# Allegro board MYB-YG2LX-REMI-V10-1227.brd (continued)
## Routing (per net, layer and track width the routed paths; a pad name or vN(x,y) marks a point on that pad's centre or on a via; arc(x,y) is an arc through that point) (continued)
TX1_DN: length 44.4
  TOP w0.13: U11.27 20.34,28.71 20.34,29.22 20.06,29.5 20.06,29.88 v1(20.23,30.04) ; U12.C4 22.64,13.77 22.64,13.92 22.3,14.27 22.3,14.89 v1(22.12,15.06)
  ART03 w0.109: v1(22.12,15.06) 22.29,15.22 22.29,15.95 20.03,18.21 17.7,18.21 17,18.91 17,19.34 17.32,19.65 17.32,19.81 17.01,20.12 16.85,20.12 16.6,19.86 16.14,19.86 14.45,21.56 14.45,26.49 14.83,26.87 15.87,26.87 16.18,26.57 17.06,26.57 17.47,26.98 17.47,27.6 17.36,27.71 16.71,27.71 16.4,28.01 16.4,28.37 16.3,28.48 15.11,28.48 14.81,28.78 14.81,31.06 14.05,31.82 14.05,32.24 14.55,32.74 14.98,32.74 15.77,31.95 16.12,31.95 16.53,32.37 16.53,34.22 16.84,34.52 17.58,34.52 17.88,34.22 17.88,32.72 17.99,32.61 19.76,32.61 20.06,32.31 20.06,30.21 v1(20.23,30.04)
TX1_DN_OUT: length 2.8
  TOP w0.13: U12.A4 22.61,12.45 22.46,12.31 22.46,11.98 22.13,11.64 J7.6
TX1_DP: length 44.4
  TOP w0.13: U11.28 20.01,28.7 20.01,29.08 19.73,29.36 19.73,29.88 v1(19.57,30.04) ; U12.C3 22.97,13.77 22.97,14.06 22.62,14.41 22.62,14.9 v1(22.78,15.06)
  ART03 w0.109: v1(19.57,30.04) 19.73,30.21 19.73,32.18 19.62,32.29 17.85,32.29 17.55,32.59 17.55,34.08 17.44,34.19 16.97,34.19 16.86,34.08 16.86,32.23 16.25,31.62 15.64,31.62 14.84,32.42 14.69,32.42 14.38,32.11 14.38,31.95 15.13,31.2 15.13,28.91 15.24,28.8 16.43,28.8 16.73,28.5 16.73,28.15 16.84,28.04 17.5,28.04 17.8,27.74 17.8,26.85 17.19,26.24 16.04,26.24 15.74,26.55 14.97,26.55 14.78,26.36 14.78,21.69 16.28,20.19 16.46,20.19 16.72,20.44 17.14,20.44 17.65,19.94 17.65,19.52 17.33,19.2 17.33,19.05 17.84,18.54 20.17,18.54 22.62,16.09 22.62,15.89 22.71,15.79 23.17,15.79 23.26,15.7 23.26,15.56 23.17,15.47 22.71,15.47 22.62,15.37 22.62,15.22 v1(22.78,15.06)
TX1_DP_OUT: length 2.8
  TOP w0.13: J7.4 23.13,11.52 22.79,11.85 22.79,12.17 22.94,12.32 22.94,12.86 U12.A3
TX2_DN: length 44.6
  TOP w0.13: v1(19.31,30.56) 19.15,30.39 19.15,29.36 19.18,29.33 U11.30 ; v1(23.63,15.06) 23.79,14.9 23.79,14.37 23.44,14.02 23.44,13.77 U12.C2
  ART03 w0.109: v1(19.31,30.56) 19.15,30.73 19.15,30.99 18.85,31.29 16.93,31.29 16.51,30.87 16.51,29.56 16.83,29.24 18.18,29.24 18.51,28.91 19.55,28.91 19.66,28.8 19.66,28.02 19.55,27.91 18.71,27.91 18.41,27.61 18.41,25.63 18.2,25.42 16.15,25.42 15.74,25.02 15.74,22.3 16.07,21.97 17.2,21.97 17.52,22.3 17.52,23.87 17.63,23.98 18,23.98 18.11,23.87 18.11,20.93 18.41,20.62 19.2,20.62 19.5,20.93 19.5,22.02 19.61,22.13 21.94,22.13 22.05,22.02 22.05,21.37 21.93,21.26 20.46,21.26 20.16,20.96 20.16,19.38 22.17,17.37 22.7,17.37 23.8,16.27 23.8,15.22 v1(23.63,15.06)
TX2_DN_OUT: length 3
  TOP w0.13: J7.3 23.63,11.56 23.96,11.9 23.96,11.97 23.47,12.47 23.47,12.88 U12.A2
TX2_DP: length 44.6
  TOP w0.13: U11.31 18.78,29.33 18.82,29.36 18.82,30.39 v1(18.65,30.56) ; v1(24.29,15.06) 24.12,14.89 24.12,14.24 23.77,13.89 23.77,13.77 U12.C1
  ART03 w0.109: v1(18.65,30.56) 18.82,30.73 18.82,30.86 18.71,30.97 17.07,30.97 16.84,30.73 16.84,29.7 16.97,29.57 18.31,29.57 18.64,29.24 19.69,29.24 19.99,28.93 19.99,27.89 19.69,27.58 18.85,27.58 18.74,27.48 18.74,25.5 18.33,25.1 16.28,25.1 16.07,24.88 16.07,22.44 16.21,22.3 17.06,22.3 17.19,22.43 17.19,24.01 17.5,24.31 18.14,24.31 18.44,24.01 18.44,21.06 18.55,20.95 19.07,20.95 19.18,21.06 19.18,22.15 19.48,22.45 22.07,22.45 22.37,22.15 22.37,21.23 22.07,20.93 20.6,20.93 20.49,20.82 20.49,19.51 22.31,17.7 22.83,17.7 24.13,16.41 24.13,16.09 24.22,15.99 24.67,15.99 24.76,15.9 24.76,15.76 24.67,15.67 24.22,15.67 24.13,15.57 24.13,15.22 v1(24.29,15.06)
TX2_DP_OUT: length 2.9
  TOP w0.13: U12.A1 23.79,12.92 23.79,12.6 24.29,12.1 24.29,11.93 24.63,11.59 J7.1
TX_CKN: length 44.5
  TOP w0.13: U13.C4 19.83,13.77 19.83,13.92 19.48,14.27 19.48,14.89 v1(19.31,15.06) ; v1(22.91,30.03) 22.75,29.86 22.75,29.36 22.78,29.33 U11.21
  ART03 w0.109: v1(22.91,30.03) 22.75,30.19 22.75,31.35 22.22,31.88 22.22,33.28 19.1,36.4 15.64,36.4 14.8,35.56 13.83,35.56 11.81,33.54 11.81,17.92 13.35,16.39 19.11,16.39 19.47,16.02 19.47,15.22 v1(19.31,15.06)
TX_CKN_OUT: length 2.9
  TOP w0.13: U13.A4 19.83,12.89 19.83,12.55 19.49,12.21 19.49,11.9 19.13,11.54 J7.12
TX_CKP: length 44.5
  TOP w0.13: v1(22.25,30.03) 22.42,29.86 22.42,29.36 22.38,29.33 U11.22 ; U13.C3 20.16,13.77 20.16,14.05 19.81,14.4 19.81,14.9 v1(19.97,15.06)
  ART03 w0.109: v1(19.97,15.06) 19.8,15.22 19.8,15.44 19.9,15.54 20.37,15.54 20.47,15.64 20.47,15.77 20.37,15.87 19.9,15.87 19.8,15.96 19.8,16.16 19.25,16.71 13.48,16.71 12.14,18.06 12.14,33.4 13.97,35.23 14.94,35.23 15.78,36.07 18.97,36.07 21.89,33.14 21.89,31.74 22.42,31.22 22.42,30.19 v1(22.25,30.03)
TX_CKP_OUT: length 2.9
  TOP w0.13: U13.A3 20.16,12.9 20.16,12.42 19.81,12.07 19.81,11.81 20.13,11.49 J7.10
TX_HPD: length 26.9
  TOP w0.152: U11.14 25.59,27.12 25.9,27.43 25.9,28.5 24.89,29.51 v1(24.81,29.51)
  ART03 w0.152: v1(24.81,29.51) 24.81,28.96 23.85,27.99 23.85,17.35 25.09,16.1 25.09,15.21 22.55,12.67 v1(21.79,12.67)
  BOTTOM w0.152: v1(21.79,12.67) 21.36,12.24 20.65,12.24 20.49,12.09 Q5.2 19.06,11.2 R105.1
UART_CTS: length 4.6
  TOP w0.152: U22.42 v1(30.93,51.2)
  BOTTOM w0.152: v1(30.93,51.2) 30.93,51.05 30.53,50.65 29.87,50.65 29.34,51.18 U22.42 R222.2
UART_RTS: length 1.9
  TOP w0.152: U22.43 v1(30.3,52.1)
  BOTTOM w0.152: U22.43 v1(30.3,52.1)
USB2CC1: length 7
  BOTTOM w0.152: U9.2 80.07,11.85 79.45,11.23 79.45,10.98 79.13,10.67 78.2,10.67 78.02,10.48 R40.2 C47.1 78.02,8.75 78.25,8.51 78.83,8.51 79.21,8.13 R41.1
USB2CC2: length 10.6
  ART04 w0.152: v1(82.34,8.08) 81.53,8.89 81.53,10.21 v1(79.45,12.29)
  BOTTOM w0.152: C48.1 R47.2 79.45,12.41 v1(79.45,12.29) 80.01,12.85 U9.4 ; R42.1 80.83,7.61 81.3,8.08 v1(82.34,8.08)
WIFI_SD1_CLK: length 31.5
  TOP w0.152: U24.6 35.14,50.26 35.45,50.57 v1(35.45,50.9) ; R223.2 v1(24.34,41.38)
  ART03 w0.152: v1(24.34,41.38) 24.68,41.38 24.81,41.5 24.81,42.24 24.66,42.39 23.72,42.39 23.57,42.55 23.57,42.85 23.72,43 25.02,43 25.17,43.16 25.17,44.5 26.11,45.44 26.4,45.44 26.55,45.59 26.55,45.77 26.7,45.92 27.01,45.92 27.16,45.77 27.16,45.59 27.31,45.44 28.24,45.44 28.67,45.87 28.67,46.73 28.83,46.88 29.69,46.88 29.84,47.04 29.84,47.34 29.69,47.49 28.83,47.49 28.67,47.65 28.67,47.85 28.9,48.08 30.88,48.08 31.95,49.15 31.95,50.67 32.18,50.9 32.52,50.9 32.67,50.75 32.67,49.23 32.82,49.07 33.13,49.07 33.28,49.23 33.28,50.75 33.43,50.9 33.92,50.9 34.07,50.75 34.07,50.14 34.22,49.99 34.53,49.99 34.68,50.14 34.68,50.75 34.83,50.9 v1(35.45,50.9)
WIFI_SD1_CMD: length 32.8
  TOP w0.152: R224.2 v1(26.12,41.36) ; v1(36.29,53.57) 36.11,53.57 34.75,52.21 33.42,52.21 U24.3
  ART03 w0.152: v1(36.29,53.57) 37,52.86 37,52.03 36.85,51.87 36.5,51.87 36.34,51.72 36.34,51.42 36.5,51.27 36.85,51.27 37,51.11 37,49.61 36.75,49.35 34.21,49.35 34.06,49.2 34.06,48.77 34.21,48.62 34.54,48.62 34.69,48.46 34.69,47.93 34.54,47.78 32.38,47.78 31.54,46.94 30.86,46.94 29.5,45.58 29.5,45.37 29.91,44.96 29.91,44.74 29.69,44.53 29.48,44.53 29.07,44.94 28.85,44.94 28.47,44.55 28.47,44.07 28.27,43.87 26.3,43.87 26.12,43.69 26.12,43.34 26.28,43.19 28.32,43.19 28.47,43.03 28.47,42.73 28.32,42.58 26.27,42.58 26.12,42.42 v1(26.12,41.36)
WIFI_SD1_D0: length 38.4
  TOP w0.152: R225.2 17.23,41.72 18,40.94 20.32,40.94 20.49,41.12 v1(20.49,41.25)
  ART03 w0.152: v1(35.43,48.84) 35.63,48.65 35.63,47.57 35.3,47.24 35.3,46.76 35.15,46.61 34.86,46.61 34.71,46.76 34.71,47.14 34.55,47.29 34.25,47.29 34.1,47.14 34.1,46.76 33.95,46.61 32.15,46.61 31.34,45.8 30.98,45.8 30.55,45.36 30.55,44.58 30.15,44.17 29.08,44.17 28.93,44.02 28.93,42.04 28.77,41.88 27.71,41.88 27.45,41.63 27.45,41.07 27.02,40.64 23.29,40.64 23.01,40.92 23.01,41.68 22.86,41.83 22.73,41.83 22.58,41.99 22.58,42.82 22.42,42.98 22.12,42.98 21.97,42.82 21.97,41.99 21.81,41.83 21.33,41.83 21.18,41.99 21.18,43.36 21.03,43.51 20.65,43.51 20.49,43.36 20.49,43.2 20.34,43.05 19.33,43.05 19.17,42.9 19.17,42.59 19.33,42.44 20.34,42.44 20.49,42.29 v1(20.49,41.25)
  BOTTOM w0.152: U23.3 34.45,50.26 35.46,49.24 35.46,48.88 v1(35.43,48.84)
WIFI_SD1_D1: length 42.8
  TOP w0.152: R226.2 18.12,41.64 18.41,41.35 v1(18.67,41.35)
  ART03 w0.152: v1(35.67,51.98) 35.13,51.98 34.98,52.13 34.98,52.88 34.83,53.04 34.52,53.04 34.37,52.88 34.37,52.13 34.22,51.98 33.91,51.98 33.76,52.13 33.76,52.88 33.61,53.04 33.3,53.04 33.15,52.88 33.15,52.13 33,51.98 32.69,51.98 32.54,52.13 32.54,52.88 32.39,53.04 32.08,53.04 31.93,52.88 31.93,52.13 31.78,51.98 31.63,51.98 31.48,51.83 31.48,51.17 31.06,50.75 30.02,50.75 29.87,50.6 29.87,49.02 29.71,48.87 29.43,48.87 29.25,49.05 29.25,50.93 29.1,51.08 28.79,51.08 28.64,50.93 28.64,49.07 24.74,45.16 23.83,45.16 23.68,45.01 23.68,44.3 23.52,44.15 23.22,44.15 23.07,44.3 23.07,45.52 22.92,45.67 22.55,45.67 22.4,45.52 22.4,44.27 22.17,44.04 21.94,44.04 21.79,44.2 21.79,44.83 21.64,44.98 21.33,44.98 21.18,44.83 21.18,44.2 21.03,44.04 20.5,44.04 20.34,44.2 20.34,44.73 20.19,44.88 19.89,44.88 19.73,44.73 19.73,44.2 19.58,44.04 18.87,44.04 18.67,43.84 v1(18.67,41.35)
  BOTTOM w0.152: U23.6 33.42,52.21 35.44,52.21 v1(35.67,51.98)
WIFI_SD1_D2: length 38.1
  TOP w0.152: v1(41.5,52.7) 42.72,51.49 42.72,49.71 42.19,49.17 41.14,49.17 40.81,48.84 40.81,48.06 38.35,45.59 35,45.59 v1(34.81,45.4) ; v1(21.1,41.27) 21.1,41.66 20.79,41.96 R227.2
  ART03 w0.152: v1(21.1,41.27) 21.94,40.44 21.94,38.89 23.24,37.59 28.24,37.59 29.71,39.07 29.71,40.28 30.32,40.89 30.32,42.85 31.82,44.35 32.43,44.35 33.32,45.24 34.65,45.24 34.81,45.39 v1(34.81,45.4)
  BOTTOM w0.152: U23.10 39.22,52.86 41.35,52.86 v1(41.5,52.7)
WIFI_SD1_D3: length 35.9
  TOP w0.152: R228.2 v1(22.56,41.31) ; v1(34.67,45.95) 34.95,45.95 34.98,45.99 36.2,45.99 36.52,46.3 36.52,47.04 36.67,47.19 36.98,47.19 37.13,47.04 37.13,46.38 37.28,46.23 38.35,46.23 40.33,48.21 40.33,49.56 40.79,50.01 41.96,50.01 42.24,50.29 42.24,50.65 v1(41.7,51.18)
  ART03 w0.152: v1(22.56,41.31) 22.37,41.12 22.37,39.04 22.88,38.53 27.2,38.53 27.63,38.96 27.63,40.41 28.49,41.27 29.31,41.27 29.76,41.73 29.76,43.05 32.86,46.15 34.47,46.15 v1(34.67,45.95)
  BOTTOM w0.152: v1(41.7,51.18) 40.64,51.18 40.36,50.91 U23.13
N23563869: length 1.7
  TOP w0.152: J2.4 11.82,44.92 11.99,45.09 12.62,45.09 R24.2
N23563890: length 2
  TOP w0.152: R25.2 12.67,46.02 12.06,45.42 J2.5
N23565746: length 2.1
  TOP w0.152: J2.2 12.73,43.92 R23.2
N23602849: length 11
  TOP w0.152: S1.3 S1.4 v1(107.91,6.16)
  BOTTOM w0.152: v1(107.91,6.16) 107.91,4.96 C159.1 108.89,3.05 D37.2 110.66,2.65 D36.2
N23726017: length 1.3
  BOTTOM w0.152: Y1.3 9.83,47.45 R21.1
N23737816: length 2.4
  TOP w0.152: J2.9 12.42,47.42 12.57,47.57 v1(12.57,47.65)
  BOTTOM w0.152: R21.2 12.37,47.45 v1(12.57,47.65)
N23945057: length 2.4
  TOP w0.152: v1(106.19,6.16) 106.16,6.13 D39.1
  BOTTOM w0.152: R250.2 v1(106.19,6.16)
N23945063: length 1.8
  TOP w0.152: v1(40.03,46.67) D42.1
  BOTTOM w0.152: R254.2 40.04,46.69 v1(40.03,46.67)
N23950761: length 3.1
  BOTTOM w0.152: R256.2 R255.2 74.32,68.14 74.5,67.96 U25.7
N23950837: length 1.8
  BOTTOM w0.152: U25.13 82.48,61.62 R252.2
N23950839: length 2.3
  BOTTOM w0.152: R251.2 73.58,61.61 U25.2
N24039867: length 2.2
  TOP w0.152: U7.10 18.39,31.47 18.29,31.56 R26.2
N24681904: length 5.2
  TOP w0.381: R102.1 18.7,13.58 v1(18.54,13.74) 16.23,13.74 16.05,13.56 R101.1
  BOTTOM w0.381: D26.2 v1(18.54,13.74)
N24681967: length 4.6
  TOP w0.254: J7.18 16.13,11.71 15.14,12.69 v1(15.14,13.7)
  BOTTOM w0.381: D25.2 v1(15.14,13.7)
N24681971: length 1.5
  BOTTOM w0.381: R103.2 20.36,9.41 Q5.1
N24683528: length 1.5
  BOTTOM w0.152: U14.5 17.09,4.51 R111.2
N24683530: length 1.7
  BOTTOM w0.152: U14.4 23.24,4.51 R112.2
N24696102: length 13.2
  TOP w0.152: U16.26 91.41,19.56 90.95,20.02 90.95,25.58 91.79,26.42 91.79,26.88 91.64,27.03 91.31,27.03 91.16,27.18 91.16,27.49 91.31,27.64 91.64,27.64 91.79,27.79 91.79,27.99 91.39,28.4 v1(90.95,28.4)
  BOTTOM w0.152: v1(90.95,28.4) 91.26,28.7 91.26,29.06 91.03,29.29 R147.1
N24696119: length 15.9
  TOP w0.152: U16.23 92.96,22.35 92.27,23.04 92.27,24.87 93.01,25.6 93.01,29.39 92.38,30.02 92.38,30.94 92.22,31.09 91.87,31.09 91.72,30.94 v1(91.72,30.12)
  BOTTOM w0.152: R150.1 89.66,32.18 v1(91.72,30.12)
N24696121: length 15.8
  TOP w0.152: v1(89.92,31.13) 89.92,31.98 90.1,32.16 90.75,32.16 90.9,32 90.9,30.05 91.41,29.54 92.3,29.54 92.63,29.21 92.63,25.96 91.82,25.15 91.82,22.89 92.63,22.07 92.63,21.46 92.56,21.39 U16.24
  BOTTOM w0.152: R149.1 89.87,31.18 v1(89.92,31.13)
N24696123: length 16.2
  TOP w0.152: U16.25 91.79,19.99 91.79,22.16 91.36,22.59 91.36,25.45 92.2,26.29 92.2,28.75 91.87,29.08 90.98,29.08 90.83,29.24 90.83,29.49 90.67,29.64 90.39,29.64 90.24,29.49 90.24,29.06 90.12,28.93 89.91,28.93 89.74,28.75 89.43,28.75 89.28,28.91 89.28,30.03 89.43,30.18 v1(90.04,30.18)
  BOTTOM w0.152: R148.1 v1(90.04,30.18)
N24696137: length 12.6
  TOP w0.152: v1(89.84,25.43) 89.56,25.15 89.56,20.52 91.32,18.76 U16.28
  BOTTOM w0.152: R145.1 86.66,24.22 86.91,24.47 86.91,24.99 87.38,25.46 87.64,25.46 87.91,25.73 89.53,25.73 v1(89.84,25.43)
N24696177: length 6.4
  TOP w0.152: C121.2 95.03,10.56 Y7.3 95.98,11.5 95.98,13.12 R153.1 95.76,13.93 U16.45
N24696297: length 4.8
  TOP w0.152: C128.1 97.34,12.35 Y7.1 96.56,12.35 96.35,12.56 R153.2 96.16,13.83 U16.46
N24696307: length 4.1
  TOP w0.152: U16.48 96.96,14.54 98.14,13.36 99.13,13.36 99.7,12.79 R158.2
N24696859: length 14.4
  TOP w0.152: U16.19 94.56,22.3 94.99,22.73 v1(94.99,24.03)
  BOTTOM w0.152: v1(94.99,24.03) 94.99,25.52 94.84,25.67 94.36,25.67 94.2,25.82 94.2,26.13 94.36,26.28 94.84,26.28 94.99,26.43 94.99,26.67 94.66,27 91.66,27 91.03,26.37 91.03,25.88 90.17,25.02 89.39,25.02 R142.1
N24696861: length 14.8
  TOP w0.152: U16.21 93.76,22.52 94,22.76 94,23.85 94.88,24.73 T15.1 95.54,24.41 v1(95.54,23.63)
  BOTTOM w0.152: v1(95.54,23.63) 95.07,23.16 94.34,23.16 93.98,23.53 93.98,24.77 93.65,25.1 91.5,25.1 90.11,23.7 89.75,23.7 R140.1
N24696875: length 14.3
  TOP w0.152: v1(95.42,22.73) 94.96,22.27 U16.18
  BOTTOM w0.152: R143.1 89.92,22.18 90.06,22.33 90.06,22.54 89.82,22.78 89.82,23 90.04,23.21 90.25,23.21 90.6,22.87 90.81,22.87 91.11,23.16 91.27,23.16 91.43,23.32 91.43,24.43 91.58,24.59 91.88,24.59 92.04,24.43 92.04,23.32 92.19,23.16 92.49,23.16 92.64,23.32 92.64,24.03 92.8,24.18 93.1,24.18 93.25,24.03 93.25,22.95 93.47,22.73 v1(95.42,22.73)
N24696881: length 14.8
  TOP w0.152: v1(96.36,22.71) 96.36,22.5 95.76,21.9 U16.16
  BOTTOM w0.152: v1(96.36,22.71) 95.75,22.1 95.75,21.39 95.6,21.23 95,21.23 94.85,21.39 94.85,22.2 94.7,22.35 94.39,22.35 94.24,22.2 94.24,21.39 94.09,21.23 93.26,21.23 93.11,21.39 93.11,21.62 93.26,21.77 93.49,21.77 93.62,21.89 93.62,22.2 93.49,22.33 93.04,22.33 92.66,22.71 91.23,22.71 89.71,21.18 R139.1
N24696883: length 14.7
  TOP w0.152: U16.17 95.36,21.96 95.86,22.45 95.86,22.78 v1(96.39,23.32)
  BOTTOM w0.152: v1(96.39,23.32) 96.82,22.89 96.82,22.56 96.14,21.87 96.14,21.08 95.83,20.78 93.01,20.78 92.73,21.06 92.73,21.97 92.45,22.25 91.3,22.25 R144.1
N24697239:
  vias: v1(90.37,16.56) v1(90.8,16.56)
N24759045: length 2.3
  TOP w0.152: SW1.3 100.48,5.51 v1(99.77,6.22)
  BOTTOM w0.152: v1(99.77,6.22) 100.33,5.66 R60.2
N24759067: length 3.1
  TOP w0.152: SW1.1 v1(99.56,2.97)
  BOTTOM w0.152: v1(99.56,2.97) 99.59,3 R62.1 R58.2
N24759190: length 2.7
  TOP w0.152: SW1.2 v1(99.4,4.25)
  BOTTOM w0.152: R59.2 99.92,4.78 v1(99.4,4.25)
N24761427: length 4.5
  BOTTOM w0.152: R57.1 102.34,3.89 R58.1 R59.1 R60.1 101.46,5.67 R61.1 R56.1
N24775120: length 35.4
  BOTTOM w0.254: D30.2 100.32,9.08 R151.1 102.73,9.91 103.86,8.79 107.41,8.79 112.16,13.54 115.85,13.54 117.67,11.71 119.07,11.71 120.11,12.75 120.11,14.48 118.39,16.2 J9.11
N24775122: length 20.6
  BOTTOM w0.254: J9.13 117.2,14.3 112.24,14.3 107.67,9.73 104.17,9.73 102.64,11.26 D31.2 101.63,12.1 R152.1
N24775176: length 8.3
  BOTTOM w0.254: C129.1 104.83,17.55 J9.5 107.39,16.26 J9.6
N24790962: length 14.3
  TOP w0.152: U16.20 94.16,22.41 94.46,22.71 94.46,23.57 v1(94.48,23.6)
  BOTTOM w0.152: R141.1 89.96,24.18 91.23,25.45 91.72,25.45 91.87,25.6 91.87,26.47 92.02,26.62 92.33,26.62 92.48,26.47 92.48,25.6 92.63,25.45 92.94,25.45 93.09,25.6 93.09,26.47 93.24,26.62 93.55,26.62 93.7,26.47 93.7,25.6 93.85,25.45 94,25.45 94.48,24.97 v1(94.48,23.6)
N24791040: length 15
  TOP w0.152: U16.27 91.35,19.16 90.09,20.42 90.09,21.14 90.24,21.29 90.39,21.29 90.55,21.45 90.55,21.75 90.39,21.9 90.24,21.9 90.09,22.06 90.09,22.36 90.24,22.51 90.39,22.51 90.55,22.67 90.55,22.97 90.39,23.12 90.24,23.12 90.09,23.27 90.09,23.58 90.24,23.73 90.39,23.73 90.55,23.88 90.55,24.19 90.39,24.34 90.24,24.34 90.09,24.49 90.09,24.95 90.37,25.23 90.45,25.23 90.6,25.38 90.6,26.06 90.39,26.26 89.35,26.26 89.23,26.39 89.23,26.8 89.38,26.95 v1(90.41,26.95)
  BOTTOM w0.152: R146.1 89.6,26.29 90.37,26.29 90.6,26.52 90.6,26.76 v1(90.41,26.95)
N24806528: length 6.4
  TOP w0.152: U19.45 95.76,33.57 R192.1 95.98,32.76 95.98,31.13 Y8.3 93.55,30.19 C137.2
N24806541: length 4.9
  TOP w0.152: U19.46 96.16,33.46 R192.2 96.35,32.2 96.56,31.99 Y8.1 97.51,31.81 C146.2
N24806543: length 3.9
  TOP w0.152: R195.2 99.73,31.99 97.32,34.39 U19.48
N24806599:
  vias: v1(90.37,36.2) v1(90.8,36.2)
N24806654: length 33
  BOTTOM w0.254: R188.1 102.42,26.55 D32.2 106.3,27.38 111.93,33.02 116.35,33.02 117.93,31.45 119.22,31.45 119.96,32.18 119.96,34.37 118.39,35.94 J10.11
N24806656: length 19.1
  BOTTOM w0.254: D33.2 102.43,28.19 R189.1 107.33,29.03 111.91,33.6 117.53,33.6 J10.13
N24806876: length 8.2
  BOTTOM w0.254: J10.5 104.46,35.89 102.38,37.98 C140.1
N24806931: length 9
  TOP w0.152: U19.20 94.16,41.33 v1(94.2,41.38)
  BOTTOM w0.152: v1(94.2,41.38) 93.75,40.92 92.99,40.92 92.75,40.69 92.75,40.47 93.26,39.96 93.26,39.75 93.05,39.53 92.83,39.53 92.32,40.04 92.11,40.04 91.46,39.4 90.44,39.4 R180.1
N24806933: length 13.7
  TOP w0.152: v1(90.47,44.48) 90.5,44.45 90.5,43.77 90.34,43.62 90.12,43.62 89.96,43.46 89.96,43.16 90.12,43.01 90.34,43.01 90.5,42.85 90.5,42.55 90.34,42.4 90.12,42.4 89.96,42.24 89.96,41.94 90.12,41.79 90.34,41.79 90.5,41.63 90.5,41.33 90.34,41.18 90.12,41.18 89.96,41.02 89.96,40.72 90.12,40.57 90.34,40.57 90.5,40.41 90.5,39.55 91.25,38.79 U19.27
  BOTTOM w0.152: R183.1 87.31,44.48 v1(90.47,44.48)
N24807160: length 14.1
  TOP w0.152: U19.26 91.33,39.19 90.98,39.55 90.98,43.99 92.18,45.19 92.18,46.17 90.06,48.29 90.06,49.45 v1(89.81,49.71)
  BOTTOM w0.152: R184.1 89.11,50.4 v1(89.81,49.71)
N24807177: length 14.6
  TOP w0.152: U19.23 92.96,41.02 92.91,41.07 92.91,44.25 93.29,44.63 93.29,46.89 v1(93,47.18)
  BOTTOM w0.152: v1(93,47.18) 92.36,47.18 92.21,47.03 92.21,46.23 92.06,46.08 91.75,46.08 91.6,46.23 91.6,47.03 91.45,47.18 91.14,47.18 90.99,47.03 90.99,46.23 90.84,46.08 90.53,46.08 90.38,46.23 90.38,47.03 90.23,47.18 R187.1
N24807179: length 14.6
  TOP w0.152: v1(92.2,48.18) 92.2,47.35 92.99,46.56 92.99,44.86 92.56,44.43 92.56,43.96 92.41,43.81 91.99,43.81 91.84,43.66 91.84,43.35 91.99,43.2 92.41,43.2 92.56,43.05 U19.24
  BOTTOM w0.152: v1(92.2,48.18) 91.64,48.74 91.33,48.74 91.18,48.59 91.18,47.83 91.03,47.68 90.72,47.68 90.57,47.83 90.57,48.59 90.42,48.74 89.79,48.74 R186.1
N24807181: length 14.7
  TOP w0.152: v1(91.76,49.18) 91.76,47.15 92.58,46.33 92.58,45.01 91.44,43.87 91.44,42.98 91.59,42.83 91.87,42.83 92.02,42.67 92.02,42.37 91.87,42.22 91.59,42.22 91.44,42.06 91.44,41.76 91.59,41.61 91.87,41.61 92.02,41.45 92.02,41.15 91.87,41 91.61,41 91.46,40.84 91.46,40.28 91.76,39.98 U19.25
  BOTTOM w0.152: R185.1 v1(91.76,49.18)
N24807187: length 16.1
  TOP w0.152: U19.28 91.17,38.39 89.29,40.27 89.29,44.58 89.45,44.74 90.04,44.74 90.19,44.89 90.19,45.19 90.04,45.35 89.45,45.35 89.29,45.5 v1(89.29,45.83) 91.48,45.83 T18.1
  BOTTOM w0.152: v1(89.29,45.83) 88.87,45.41 R182.1
N24807847: length 9.4
  TOP w0.152: U19.19 94.56,41.02 94.61,41.07 94.61,43.03 v1(94.31,43.33)
  BOTTOM w0.152: v1(94.31,43.33) 93.82,42.85 91.14,42.85 90.99,42.7 90.99,42.44 90.84,42.29 90.54,42.29 90.38,42.44 90.38,42.7 90.23,42.85 89.9,42.85 R177.1
N24807849: length 10.1
  TOP w0.152: T17.1 93.82,43.59 v1(93.57,43.33) 93.57,41.94 93.8,41.71 93.8,41 93.76,40.96 U19.21
  BOTTOM w0.152: v1(93.57,43.33) 93.14,43.33 92.99,43.48 92.99,44.2 92.83,44.35 92.53,44.35 92.38,44.2 92.38,43.48 92.22,43.33 89.38,43.33 R176.1
N24807859: length 9.3
  TOP w0.152: v1(95.37,42.72) 94.96,42.31 U19.18
  BOTTOM w0.152: R181.1 90.53,41.18 91.84,42.49 95.14,42.49 v1(95.37,42.72)
N24807877: length 9.7
  TOP w0.152: v1(96.03,41.91) 95.76,41.64 U19.16
  BOTTOM w0.152: R179.1 89.8,39.75 91.06,39.75 93.09,41.78 94.56,41.78 94.76,41.58 95.7,41.58 v1(96.03,41.91)
N24807879: length 9.4
  TOP w0.152: U19.17 95.36,42.02 v1(95.42,42.09)
  BOTTOM w0.152: R178.1 90.85,40.18 91.73,41.06 91.73,41.28 91.59,41.42 91.59,41.63 91.8,41.85 92.02,41.85 92.16,41.71 92.38,41.71 92.83,42.16 95.35,42.16 v1(95.42,42.09)
N24944194: length 3.8
  BOTTOM w0.152: R75.2 17.45,52.57 R71.2 17.46,53.31 D21.2 17.46,54.78 18.15,55.46 J5.5
N25256263: length 10
  BOTTOM w0.254: J10.6 105,37.16 103.22,38.94 103.22,41.6 C141.1
N25318172: length 5.3
  TOP w0.152: U11.54 20.38,19.74 R77.1 20.14,18.33 20.41,18.07 Y3.3 22.45,18.07 C70.1
N25318239: length 7.3
  TOP w0.152: C71.1 18.63,16.27 Y3.1 19.66,17.29 19.66,19.11 R77.2 19.26,19.62 19.98,20.34 U11.53
N25318297: length 2.1
  TOP w0.152: U11.61 23.18,20.26 R78.2
N25318324: length 2.5
  TOP w0.152: U11.62 23.58,20.33 24,19.91 24.41,19.91 R79.2
N25318354: length 3.2
  TOP w0.152: U11.64 24.38,20.75 24.58,20.55 25.56,20.55 R81.2
N25318494: length 3.1
  TOP w0.13: R88.1 27.31,20.91 27.01,20.91 25.97,21.95 25.83,21.95 25.79,21.92 U11.1
N25318514: length 3
  TOP w0.13: U11.2 25.79,22.32 25.83,22.28 26.1,22.28 27.14,21.24 27.37,21.24 R82.1
N25318534: length 2.7
  TOP w0.13: R89.1 27.32,22.68 26.58,22.68 26.51,22.75 25.83,22.75 25.79,22.72 U11.3
N25318541: length 2.6
  TOP w0.13: U11.4 25.79,23.12 25.83,23.08 26.65,23.08 26.72,23.01 27.37,23.01 R90.1
N25318586: length 2.7
  TOP w0.13: R93.1 27.34,24.44 26.45,24.44 26.37,24.35 25.83,24.35 25.79,24.32 U11.7
N25318611: length 2.7
  TOP w0.13: R95.1 27.34,24.76 26.32,24.76 26.23,24.68 25.83,24.68 25.79,24.72 U11.8
N25318630: length 3
  TOP w0.13: U11.9 25.79,25.12 25.83,25.15 26.27,25.15 27.25,26.14 27.42,26.14 R96.1
N25318650: length 3.1
  TOP w0.13: U11.10 25.79,25.52 25.83,25.48 26.13,25.48 27.12,26.47 27.27,26.47 R97.1
N25318670: length 4
  TOP w0.13: U11.11 25.79,25.92 25.83,25.95 26.08,25.95 27,26.87 27,27.81 27.16,27.97 27.37,27.97 R98.1
N25318677: length 4
  TOP w0.13: U11.12 25.79,26.32 25.83,26.28 25.94,26.28 26.67,27.01 26.67,27.94 27.02,28.3 27.32,28.3 R99.1
N25318682: length 4.4
  TOP w0.152: R100.2 27.2,29.49 26.31,28.6 26.31,27.3 25.72,26.72 U11.13
N25318705: length 1.3
  TOP w0.152: C72.1 16.38,27.12 U11.35
N25392814: length 2.4
  TOP w0.152: v1(104.06,6.1) 104.04,6.08 D41.1
  BOTTOM w0.152: R253.2 v1(104.06,6.1)
N25530834: length 1.6
  BOTTOM w0.381: Y6.1 56.94,15.08 R135.2
N25530860: length 1.4
  BOTTOM w0.152: Y6.3 60.73,13.3 R136.1
N25531113: length 1.6
  BOTTOM w0.381: Y5.4 50.14,13.42 C110.1
N25531117: length 1.6
  BOTTOM w0.381: R133.2 50.17,15.2 Y5.1
N25531143: length 1.7
  BOTTOM w0.152: Y5.3 52.57,13.32 R134.1
N25785637: length 2.5
  TOP w0.152: SW1.4 v1(100.74,7.62)
  BOTTOM w0.152: v1(100.74,7.62) 101.27,7.62 R61.2 R63.1
N25800737: length 3.2
  BOTTOM w0.152: R249.2 84.73,65.84 84.31,65.42 U25.10
N25931049: length 2.4
  TOP w0.152: J6.27 12.72,29.12 R86.2
N25931053: length 9.7
  TOP w0.152: R91.2 12.44,38.91 9.14,35.61 9.14,33.15 10.16,32.12 J6.33
N25931055: length 8.2
  TOP w0.152: J6.34 10.2,32.62 9.44,33.38 9.44,35.38 12.09,38.02 R92.2
N25931057: length 2.3
  TOP w0.152: J6.36 12.95,33.62 R94.2
N25931062: length 2.2
  TOP w0.152: R87.2 13.11,29.62 J6.28
N25991714: length 5.6
  TOP w0.254: v1(66.37,8.36) 66.38,8.36 66.63,8.1 J1.B6 66.63,6.77 66.37,6.5 65.99,6.5 65.63,6.85 J1.A6
  BOTTOM w0.152: D5.2 66.37,7.96 v1(66.37,8.36) 66.37,8.41 65.83,8.94 U2.8
N25991722: length 4.6
  TOP w0.254: J1.B7 65.13,8.11 v1(65.43,8.41) 65.46,8.38 65.68,8.38 66.13,7.93 J1.A7
  BOTTOM w0.152: U2.9 v1(65.43,8.41) 65.43,7.82 D4.2
N26002192: length 6.5
  BOTTOM w0.203: U2.1 67.28,12.7 67.65,13.07 ; U2.19 66.23,13.05 66.54,13.36
  BOTTOM w0.381: R3.1 R9.2 68.79,11.93 67.36,13.36 66.54,13.36
N26033210: length 4.2
  TOP w0.381: C12.1 31.09,42.5 31.1,42.5 R15.2 31.99,42.13 R12.1 ; R12.1 32.04,42.17 U3.4 ; R12.1 R10.2
N26033286: length 1.9
  TOP w0.381: C18.1 36.54,44.57 U3.1
N26033313: length 3.7
  TOP w0.381: R14.1 R11.2 C19.2 33.34,46.48 U3.3
N26043102: length 3.1
  TOP w0.381: U4.5 37.31,32.55 R17.1 C24.1 R19.1
N26043190: length 4.7
  TOP w0.381: U4.1 37.32,28.94 37.72,28.54 R18.1 R16.2 C178.1 38.19,27.08 38.18,27.09 R8.2
N26044739: length 7.5
  TOP w0.305: R234.1 30.73,58.52 30.35,58.14 30.35,56.77 30.18,56.6 U22.48 28.32,56.6 28.04,56.31 28.04,55.17 28.41,54.8 U22.46
N26044834: length 3.4
  TOP w0.432: C150.2 C149.1 D34.2 J18.1
N26044878: length 3.4
  TOP w0.432: C151.2 C152.1 D35.2 J17.1
N26044892: length 1.8
  TOP w0.432: C150.1 U22.9
N26044934: length 21.2
  TOP w0.152: U22.15 18.44,55.7 22.54,51.6 22.54,47.32 22.82,47.04 24.05,47.04 25.24,45.85 25.24,44.4 25.65,43.99 27.02,43.99 28.14,42.87 R211.1 R217.1
N26045129: length 2.1
  TOP w0.152: v1(30.32,50.16) 30.19,50.3 U22.41
  BOTTOM w0.152: v1(30.32,50.16) 30.19,50.3 U22.41
N26045131: length 1.9
  TOP w0.152: U22.40 v1(30.3,49.4)
  BOTTOM w0.152: U22.40 v1(30.3,49.4)
N26045353: length 1.9
  BOTTOM w0.381: R231.2 23.25,52.09 Y9.1
N26045413: length 2.5
  BOTTOM w0.152: R232.1 24.82,49.87 25.24,50.29 Y9.3
N26045441: length 57.9
  TOP w0.152: U22.49 28.48,57.5 v1(28.09,57.89)
  ART04 w0.152: v1(28.09,57.89) 29.84,57.89 30.48,58.52 37.72,58.52 40.48,61.29 41.12,61.29 46.5,66.67 48.97,66.67 49.6,66.04 v1(49.6,65.25)
  BOTTOM w0.152: R216.1 74.47,54.71 73.45,55.73 61.9,55.73 54.56,63.07 51.79,63.07 v1(49.6,65.25)
N26045646: length 1.8
  TOP w0.432: C151.1 U22.2
N26048215: length 2.8
  TOP w0.254: U15.11 37.58,17.95 36.76,17.12 CT2.1
N26048218: length 2.9
  TOP w0.254: U15.12 38.03,17.93 39.06,16.9 CT1.1
N26048225: length 2
  TOP w0.152: U15.5 35.22,20.38 R121.2
N26048227: length 1.6
  TOP w0.152: R122.2 34.34,19.48 U15.7
N26048236: length 3.5
  TOP w0.152: R119.2 C96.1 38.22,24.46 37.72,23.95 37.44,23.95 36.68,23.19 U15.27
N26048238: length 3.2
  TOP w0.152: U15.28 36.23,23.45 36.7,23.93 36.93,23.93 37.42,24.42 C95.1 R118.2
N26048526: length 4.5
  TOP w0.152: v1(38.15,23.77) 38.02,23.65 37.56,23.65 37.13,23.21 U15.26
  BOTTOM w0.152: v1(38.15,23.77) 38.47,23.77 38.62,23.62 R117.2 R120.2 R115.2
N26048542: length 2
  TOP w0.152: U15.20 40.23,21.73 41.03,22.53 C108.1
N26048550: length 3.6
  TOP w0.254: U15.10 37.13,18.57 36.87,18.31 35.91,18.31 35.56,18.67 v1(34.84,18.67)
  BOTTOM w0.381: C106.1 34.82,18.69 v1(34.84,18.67)
N26048576: length 1.6
  TOP w0.254: C100.1 v1(41.5,25.93)
  BOTTOM w0.254: C100.1 v1(41.5,25.93)
N26048711: length 2.3
  TOP w0.152: R126.2 34.41,19.08 36.08,19.08 U15.8
N26048728: length 1.8
  TOP w0.152: U15.6 34.78,19.93 R125.2
N26048948: length 5.3
  TOP w0.254: C99.2 42.03,23.8 40.97,23.8 40.31,23.14 39.39,23.14 39.24,23.29 38.76,23.29 38.48,23.01 U15.23
N26048966: length 1.6
  TOP w0.254: C99.1 v1(43.53,25.93)
  BOTTOM w0.254: C99.1 v1(43.53,25.93)
N26049021: length 3.9
  TOP w0.152: U15.24 38.03,23.07 38.6,23.65 39.39,23.65 39.52,23.52 40.15,23.52 40.69,24.05 C100.2
N26049089: length 2.7
  TOP w0.381: R116.1 CT1.2
N26049137: length 2.7
  TOP w0.381: R123.1 CT2.2
N26059354: length 3.8
  TOP w0.152: J3.A5 79.61,7.73 79.47,7.87 78.33,7.87 v1(78.23,7.98)
  BOTTOM w0.152: D9.2 78.33,6.48 R41.2 78.23,7.42 v1(78.23,7.98)
N26059364: length 4.4
  TOP w0.305: J3.B5 80.85,4.45 v1(81.15,4.15)
  BOTTOM w0.305: v1(81.15,4.15) 80.83,4.47 R42.2 80.84,6.12 D10.2
N26059408: length 9.7
  BOTTOM w0.152: R51.1 73.88,12.67 74.44,13.23 74.44,14.61 75.1,15.27 79.47,15.27 80.24,14.5 U9.7
N26059410: length 8.7
  BOTTOM w0.152: U9.8 81.44,14.69 81.1,15.04 80.29,15.04 79.75,15.57 74.88,15.57 74.65,15.34 R50.1
N26059424: length 2.5
  BOTTOM w0.152: U9.23 81.44,10.22 81.76,9.91 82.31,9.91 C50.1
N26059430: length 1.6
  BOTTOM w0.152: U9.5 79.48,13.35 78.97,13.86 R47.1
N26059432: length 1.9
  BOTTOM w0.152: U9.1 79.1,10.16 R40.1
N26059484: length 3
  BOTTOM w0.152: U9.21 82.44,10.37 82.95,9.86 83.96,9.86 C49.1
N26059520: length 1.8
  BOTTOM w0.152: U9.6 79.78,13.85 R52.1
N26059554: length 2.6
  BOTTOM w0.152: R45.1 R38.2 79.07,11.89 79.63,11.89 80.09,12.35 U9.3
N26059572: length 18.4
  ART03 w0.254: v1(98.17,6.48) 96.06,8.59 91.66,8.59 90.32,9.93 89.56,9.93 88.67,10.82 v1(87.19,10.82)
  BOTTOM w0.152: 84.27,10.16 83.18,10.16 82.94,10.4 U9.20
  BOTTOM w0.254: v1(98.17,6.48) 97.74,6.05 R37.2 ; v1(87.19,10.82) 84.93,10.82 84.27,10.16
N26059598: length 11.7
  ART03 w0.254: v1(85.04,12.32) 85.85,11.51 88.72,11.51 89.15,11.07 91.54,11.07 92.93,9.68 v1(93.95,9.68)
  BOTTOM w0.254: v1(85.04,12.32) 84.91,12.19 84.91,11.58 84.67,11.35 U9.18
N26059749: length 1.5
  BOTTOM w0.152: R49.1 85.61,13.85 U9.13
N26081456: length 1.6
  TOP w0.381: Y4.1 31.14,29.25 R113.2
N26081482: length 2.2
  TOP w0.152: Y4.3 34.54,25.36 R114.1
N26098482: length 29.9
  BOTTOM w0.152: R260.2 9.26,24.98 D44.2 9.26,23.78 9.7,23.34 10.41,23.34 10.77,23.7 10.77,24.97 11.25,25.45 11.25,28.4 12.67,29.82 14.12,29.82 15.9,31.6 20.37,31.6 22.04,33.27 22.86,33.27 23.57,33.99 23.57,38.02 25.12,39.58 J15.2
N26098494: length 39.1
  BOTTOM w0.152: R258.2 9.07,17.82 D43.2 10.95,17.46 11.2,17.7 11.2,24.79 11.76,25.35 11.76,28.32 12.8,29.36 14.12,29.36 15.95,31.19 20.39,31.19 22.09,32.89 24.13,32.89 24.81,32.21 25.83,32.21 26.03,32.41 26.03,37.97 27.63,39.58 J15.1
N26098528: length 2.3
  BOTTOM w0.152: Q6.3 9.07,20.62 R258.1 R259.1
N26098578: length 2.6
  BOTTOM w0.152: R260.1 R262.1 10.08,27.21 Q7.3
N26103216: length 19.4
  BOTTOM w0.152: R266.2 13.14,35.73 D46.2 15.98,35.73 16.84,34.87 16.84,33.99 18.5,32.33 20.09,32.33 22.02,34.26 22.02,37.22 20.7,38.53 19.17,38.53 J16.2
N26103218: length 17
  BOTTOM w0.152: R264.2 13.05,32.66 D45.2 15.15,32.66 15.52,33.02 16.86,33.02 17.85,32.03 20.22,32.03 22.53,34.34 22.53,37.72 J16.1
N26103260: length 2.3
  BOTTOM w0.152: Q8.3 10.72,32.67 R264.1 R265.1
N26103310: length 2.5
  BOTTOM w0.152: R266.1 12.25,36.6 R268.1 Q9.3
N26112798: length 1.1
  BOTTOM w0.203: U8.6 48.1,19.15 R34.2
N26137432:
  vias: v1(98.8,50.95) v1(99.61,50.98)
N26147104: length 5.1
  TOP w0.152: C64.1 98.58,61.47 Y2.3 97.4,59.03 U10.10
N26147108: length 3.3
  TOP w0.152: C65.1 94.77,58.41 Y2.1 96.9,57.79 U10.11
N26155524: length 9.1
  TOP w0.155: L4.1 104.91,58.19 105.34,58.19 D11.2 105.94,58.19 107.72,58.19 108.28,57.62 108.28,55.39 108.75,54.91 109.33,54.91 J4.A2
N26155536: length 9
  TOP w0.155: L4.4 104.83,58.51 105.34,58.51 D12.2 105.94,58.51 107.85,58.51 108.61,57.76 108.61,55.52 108.89,55.24 109.33,55.24 J4.A3
N26155544: length 11.6
  TOP w0.155: L5.1 104.92,54.59 105.34,54.59 D14.2 105.96,54.61 107.05,54.61 108.98,52.68 111.05,52.68 111.58,53.21 111.58,54.76 111.73,54.91 111.95,54.91 J4.B2
N26155546: length 11.6
  TOP w0.155: J4.B3 111.95,55.24 111.6,55.24 111.25,54.9 111.25,53.35 110.91,53.01 109.11,53.01 107.18,54.94 105.91,54.94 D13.2 105.34,54.91 104.89,54.91 L5.4
N26211804: length 1.9
  BOTTOM w0.152: U2.13 63.65,11.13 T20.1
N26211815: length 3.3
  BOTTOM w0.152: U2.12 63.49,10.73 63.09,11.13 62.76,11.13 62.45,11.43 T21.1
N2605947810: length 5.1
  BOTTOM w0.152: T6.1 84.04,17.96 84.04,15.19 83.89,15.04 83.28,15.04 82.94,14.69 U9.11
N2605947811: length 3.5
  BOTTOM w0.152: T7.1 84.45,16.97 84.45,14.91 84.04,14.5 U9.12

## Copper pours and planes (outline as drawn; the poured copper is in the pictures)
GND on TOP: 7.67,41.91 9.57,41.91 9.95,41.53 9.95,36.73 9.65,36.42 7.69,36.42 7.67,36.45
GND on TOP: 13.89,43.54 15.54,43.54 15.82,43.26 15.82,41.07 15.62,40.87 13.84,40.87 13.69,41.02 13.69,43.33
GND on TOP: 7.87,58.22 9.47,58.22 9.88,58.62 11.12,58.62 13.13,60.63 14.68,60.63 15.57,59.74 15.57,55.24 15.82,54.99 15.82,54.46 12.86,54.46 11.83,55.49 10.37,55.49 9.93,55.04 9.93,45.62 7.87,45.62
GND on TOP: 100.78,51.71 101.65,51.71 102.08,52.15 102.08,52.48 102.15,52.55 103.58,52.55 103.91,52.22 103.91,49.23 103.55,48.87 100.81,48.87 100.48,49.2 100.48,51.41
GND on TOP: 47.6,53.85 43.68,53.85 43.46,53.62 41.98,53.62 41.65,53.95 41.65,55.8 42.95,57.1 53.59,57.1 53.84,56.85 53.84,54.25 52.88,53.29 48.15,53.29
GND on TOP: 93.65,13.59 94.66,13.59 95.3,14.22 97.58,14.22 98.14,13.67 99.28,13.67 100.17,12.78 100.17,10.34 98.5,8.66 92.5,8.66 91.39,9.78 91.39,12.22 93.26,12.22 93.65,12.6
GND on TOP: 83.1,8.41 84.6,8.41 84.71,8.31 84.71,7.92 84.58,7.8 83.54,7.8 83.33,7.59 83.33,7.04 83.28,6.99 82.95,6.99 82.93,7.01 82.93,8.23
GND on TOP: 17.04,58.85 12.85,58.85 12.29,59.41 12.29,69.14 12.65,69.49 39.12,69.49 39.12,64.12 38.78,63.78 38.78,62.23 38.35,61.8 38.35,57.38 36.04,55.07 34.46,55.07 32.56,56.97 32.56,60.05 31.75,60.86 29.33,60.86 26.67,58.19 26.67,53.49 28.49,51.66 28.49,47.88 28.16,47.55 26.67,47.55 25.73,46.61 23.19,46.61 22.96,46.84 22.96,51.38 18.31,56.03 17.65,56.03 17.4,56.29 17.4,58.5
GND on TOP: 96.21,32.28 96.21,32 96.92,31.29 99.59,31.29 100.05,31.75 100.05,32 98.83,33.22 98.83,33.83 99.41,33.83 100.78,32.46 100.78,29.87 100.05,29.13 97.84,29.13 97.61,29.36 95.2,29.36 94.89,29.06 94.89,27.66 94.46,27.23 93.62,27.23 93.42,27.43 93.42,29.31 93.37,29.36 93.34,29.36 92.83,29.87 92.83,32.13 92.88,32.18 93.95,32.18 94.36,32.59 95.91,32.59
GND on TOP: 62.25,8.15 61.95,8.46 61.16,8.46 61.08,8.53 60.3,8.53 59.91,8.92 59.91,10.06 60.04,10.19 60.63,10.19 60.7,10.26 60.7,10.57 60.75,10.62 62.23,10.62 62.86,9.98 62.86,8.92 62.68,8.74 62.76,8.66 62.76,8.15
GND on TOP: 12.44,15.95 14.83,15.95 15.26,15.52 15.26,14.38 15.19,14.3 12.54,14.3 12.32,14.53 12.32,15.82
GND on TOP: 93.49,29.11 94.64,29.11 94.76,28.98 94.76,27.23 94.64,27.1 93.47,27.1 93.42,27.15 93.42,29.03
GND on TOP: 93.85,11.91 93.85,11.3 93.68,11.14 93.15,11.14 92.93,10.92 89.38,10.92 89.25,11.05 89.25,12.04 89.43,12.22 93.54,12.22
GND on TOP: 29.99,6.27 33.32,6.27 34.08,5.51 34.08,3.61 33.7,3.23 32.13,3.23 31.77,2.87 31.77,2.77 30.3,2.77 29.76,3.3 29.76,6.05
GND on TOP: 98.83,49.28 99.64,49.28 99.84,49.07 99.84,47.75 98.5,46.41 98.07,46.41 97.99,46.48 97.99,48.41 98.83,49.25
GND on TOP: 40.36,31.32 40.36,30.4 39.29,29.34 37.72,29.34 37.36,28.98 37.36,26.39 35.91,26.39 35.91,30.3 36.52,30.3 36.67,30.45 36.67,31.34 36.72,31.39 40.28,31.39
GND on TOP: 33.68,45.92 34.29,45.92 34.62,45.59 34.62,43.05 33.65,43.05 33.55,43.15 33.55,45.8
GND on TOP: 89.86,69.47 110.99,69.47 110.99,64.16 105.41,64.16 104.48,63.23 97.57,63.23 94.84,60.5 89.53,60.5 89.43,60.6 89.43,69.04
GND on TOP: 36.09,38.2 36.65,37.64 36.65,33.93 36.45,33.73 34.87,33.73 34.46,33.32 31.07,33.32 31.07,37.96 31.31,38.2
GND on TOP: 88.08,5.05 90.27,5.05 90.6,4.72 90.6,3.17 90.27,2.84 87.3,2.84 87.04,3.1 87.04,4.01
GND on TOP: 34.51,31.32 34.74,31.09 35.23,31.09 36.22,30.1 36.22,27.66 36.85,27.03 36.85,24.23 36.5,23.88 36.5,22.61 35.96,22.07 32.94,22.07 31.47,20.6 31.47,17.78 31.24,17.55 29.05,17.55 27.83,18.77 27.83,19.74 28.37,20.27 29.33,20.27 29.64,20.57 29.64,28.73 28.98,29.39 28.98,30.38 28.47,30.89 28.47,32.94 29.18,33.66 34.51,33.66
GND on TOP: 69.82,8.46 71.12,8.46 71.55,8.03 71.55,6.5 71.8,6.25 73.88,6.25 74.21,6.58 74.21,9.35 73.81,9.75 69.49,9.75 69.44,9.7 69.44,9.42 69.39,9.37 69.39,9.17 69.24,9.02 69.24,8.26 69.34,8.15 69.51,8.15
GND on TOP: 10.77,15.37 11.27,14.86 11.27,11.66 8.53,11.66 8.53,12.47 7.67,13.34 7.67,15.37
GND on TOP: 76.45,8.2 77.67,8.2 77.82,8.05 77.82,6.88 77.26,6.88 76.32,7.82 76.32,8.08
GND on TOP: 8.56,11.81 11.27,11.81 11.27,11.3 11.02,11.05 11.02,10.49 11.07,10.44 11.07,8.08 10.68,7.68 8.8,7.68 8.56,7.92
GND on TOP: 103.04,62.46 103.04,60.66 100.53,60.66 100.38,60.81 100.38,62.56 100.45,62.64 102.87,62.64
GND on BOTTOM: 70.94,67.16 70.94,65.81 70.86,65.74 69.77,65.74 69.64,65.86 69.64,67.11 69.77,67.23 70.86,67.23
GND on BOTTOM: 90.6,4.37 90.6,2.57 90.14,2.11 88.16,2.11 87.96,2.31 87.96,4.93 88.11,5.08 89.89,5.08
GND on BOTTOM: 22.65,53.37 27,53.37 27.89,52.48 27.89,50.06 27.17,49.35 25.22,49.35 24.76,49.81 24.76,52.15 24.48,52.43 24.05,52.43 22.63,51 19.45,51 19.43,51.03 19.43,51.82 19.55,51.94 21.23,51.94
GND on BOTTOM: 25.17,14.15 25.17,13.77 25.29,13.64 25.93,13.64 25.95,13.61 32.08,13.61 32.81,14.35 32.81,15.75 33.35,16.28 37.51,16.28 37.72,16.08 37.72,15.54 37.56,15.39 34.87,15.39 34.21,14.73 34.21,12.6 33.98,12.37 19.4,12.37 19.17,12.6 19.17,14.07 19.78,14.68 24.63,14.68
GND on BOTTOM: 61.82,11.15 62.35,10.62 62.35,9.19 62.28,9.12 61.36,9.12 60.91,9.58 59.91,9.58 59.46,9.12 54.81,9.12 54.76,9.17 54.76,10.87 55.04,11.15
GND on BOTTOM: 39.62,69.44 43.07,69.44 43.18,69.34 43.18,68.2 42.95,67.97 39.57,67.97 39.54,68 39.54,69.37
GND on BOTTOM: 101.44,24.18 102.97,24.18 103.07,24.08 103.07,23.34 102.97,23.24 101.32,23.24 101.27,23.29 101.27,24
GND on BOTTOM: 66.8,9.32 66.59,9.32 66.49,9.42 66.49,10.06 66.37,10.19 65.05,10.19 64.94,10.29 64.94,11.25 64.82,11.38 63.95,11.38 63.69,11.65 63.69,12.59 63.88,12.78 64.61,12.78 64.77,12.62 64.77,12.19 65.15,11.81 66.54,11.81 66.62,11.73 66.62,10.34 66.96,9.99 67.18,9.99 67.18,9.58 67.05,9.58
GND on BOTTOM: 94.18,20.47 96.87,20.47 97.05,20.29 97.05,16.26 96.82,16.03 93.11,16.03 92.43,16.71 92.43,18.52 93.09,18.52 94.08,19.51 94.08,20.37
GND on BOTTOM: 91.51,11.89 91.72,11.68 91.72,11.07 91.54,10.9 88.08,10.9 87.88,11.1 87.88,11.76 88.01,11.89
GND on BOTTOM: 99.69,49.33 99.77,49.25 99.77,48.31 99.56,48.11 99.31,48.11 99.16,47.96 99.16,46.28 99.13,46.25 98.09,46.25 98.04,46.3 98.04,49.1 98.27,49.33
GND on BOTTOM: 41.65,55.14 43.33,55.14 43.61,54.86 43.61,54.2 43.28,53.87 43.28,51.97 43.1,51.79 42.69,51.79 42.62,51.87 42.62,52.3 42.74,52.43 42.74,53.06 42.03,53.77 41.83,53.77 41.73,53.87 41.73,54.05 41.55,54.23 41.55,55.04
GND on BOTTOM: 7.9,56.82 10.56,56.82 11.68,55.7 11.68,49.38 13.13,47.93 13.13,47.5 12.7,47.07 12.7,46.28 12.59,46.18 7.82,46.18 7.64,46.35 7.64,56.57
GND on BOTTOM: 94.36,34.9 94.26,35 94.26,35.94 93.98,36.22 93.77,36.22 93.6,36.4 93.6,38.91 93.95,39.27 96.36,39.27 96.36,35.31 95.96,34.9
GND on BOTTOM: 29.43,48.87 32.53,48.87 33.09,48.31 33.09,47.19 32.79,46.89 32.79,45.01 31.16,43.38 29.84,43.38 29.41,42.95 28.75,42.95 28.62,43.08 28.62,44.04 29.23,44.65 29.23,45.85 29.13,45.95 29.13,48.56
GND on BOTTOM: 12.59,51.94 14.04,51.94 15.95,50.04 15.95,47.62 13.97,47.62 12.52,49.07 12.52,51.87
GND on BOTTOM: 72.51,67.01 72.51,64.08 72.28,63.86 71.27,63.86 71.27,65.46 70.99,65.74 69.82,65.74 69.82,67.23 72.28,67.23
GND on BOTTOM: 70.79,9.8 73.76,9.8 73.94,9.63 73.94,6.88 73.58,6.53 72.23,6.53 72.13,6.63 72.13,8.36 71.78,8.71 70.66,8.71 70.66,9.68
GND on BOTTOM: 103.04,62.46 103.04,59.74 102.71,59.41 101.11,59.41 100.38,60.15 100.38,62.56 100.45,62.64 102.87,62.64
GND on BOTTOM: 90.62,51.66 86.15,51.66 86.05,51.77 54.07,51.77 52.68,53.16 52.68,55.5 63.01,55.5 63.01,56.29 57.12,62.18 57.12,67.08 56.46,67.74 43.28,67.74 42.9,68.12 42.9,69.22 43.1,69.42 65.78,69.42 66.72,68.48 66.72,62.81 68.63,60.91 70.18,60.91 71.78,59.31 85.7,59.31 86.38,59.99 86.38,68.88 86.81,69.32 111.02,69.32 111.04,69.29 111.04,64.34 110.94,64.24 102.84,64.24 102,63.4 102,62.41 101.75,62.15 101.75,60.43 102.18,59.99 106.83,59.99 107.46,59.36 107.46,54 106.83,53.37 99.44,53.37 97.66,51.59 97.23,51.59 97.07,51.74 97.07,52.43 96.97,52.53 95.65,52.53 94.99,51.87 94.79,51.87 94.29,51.37 94.29,51.27 94.53,51.03 97.02,51.03 97.3,50.75 97.3,49.89 97.28,49.86 92.43,49.86 ; 3 cut-outs
GND on BOTTOM: 85.16,23.7 86.25,23.7 86.46,23.5 86.46,20.47 86.28,20.29 85.09,20.29 85.01,20.37 85.01,23.55
GND on BOTTOM: 11.91,69.24 13.56,69.24 14.17,68.63 14.17,57.48 11.32,54.64 7.84,54.64 7.67,54.81 7.67,58.37 7.9,58.6 9.04,58.6 9.19,58.75 9.19,62.56 9.47,62.84 10.74,62.84 11.83,63.93 11.83,69.16
GND on BOTTOM: 38.32,43.46 43.99,43.46 44.09,43.36 44.09,41.68 44.4,41.38 44.4,40.89 44.22,40.72 37.82,40.72 37.66,40.87 37.66,42.8
GND on BOTTOM: 40.97,63.02 42.26,63.02 42.36,62.92 43.4,62.92 43.89,62.43 43.89,61.24 44.17,60.96 45.36,60.96 46.1,60.22 46.1,59.05 45.94,58.9 45.44,58.9 44,60.34 43.16,60.34 42.26,61.24 40.99,61.24 40.8,61.43 40.8,62.85
GND on BOTTOM: 36.8,58.09 36.8,55.47 36.65,55.32 34.62,55.32 34.54,55.4 34.54,57.96 34.92,58.34 36.55,58.34
GND on BOTTOM: 15.21,19.33 18.74,19.33 18.97,19.1 18.97,18.24 18.49,17.75 16.07,17.75 15.38,18.45 14.51,18.45 14.37,18.59 14.37,19.2 14.49,19.32 15.2,19.32
GND on BOTTOM: 84.22,34.65 87.17,34.65 87.6,34.21 87.6,32.72 86.56,32.72 86.38,32.54 86.38,28.68 86.1,28.4 84.3,28.4 83.92,28.78 83.92,34.34
GND on BOTTOM: 52.65,55.49 52.65,53.24 52.17,52.76 49.25,52.76 48.99,52.5 48.99,50.52 48.84,50.37 47.7,50.37 47.62,50.44 47.62,56.67 48,57.05 51.09,57.05
GND on BOTTOM: 74.67,14.61 75.38,14.61 75.54,14.45 75.54,8.64 75.41,8.51 74.55,8.51 74.49,8.56 74.49,9.22 74.44,9.27 74.44,14.38
GND on BOTTOM: 101.27,51.71 101.65,51.71 102.08,52.15 102.08,52.48 102.15,52.55 103.58,52.55 103.91,52.22 103.91,49.23 103.55,48.87 101.01,48.87 100.88,49 100.88,51.33
GND on BOTTOM: 18.36,28.3 19.3,28.3 19.96,27.64 19.96,22.58 18.33,22.58 18.16,22.76 18.16,28.09
GND on BOTTOM: 7.72,40.28 9.39,40.28 9.7,39.98 9.7,38.66 9.57,38.53 7.57,38.53 7.57,40.13
GND on BOTTOM: 29.94,5.87 39.52,5.87 40.1,5.28 51.71,5.28 52.68,4.32 52.68,3.07 52.22,2.62 43.13,2.62 42.41,3.33 32.56,3.33 31.97,2.74 30.27,2.74 29.74,3.28 29.74,5.66
GND on BOTTOM: 11.88,25.45 13.86,25.45 13.99,25.32 13.99,23.22 13.69,22.91 13.69,19.46 13.05,18.82 12.21,18.82 11.63,19.41 11.63,25.2
GND on BOTTOM: 37.87,30.86 37.87,32 38.12,32.26 41.35,32.26 41.5,32.41 43.96,32.41 43.96,31.98 42.72,30.73 37.99,30.73
GND on BOTTOM: 24.53,23.85 24.3,23.62 23.92,23.62 23.85,23.55 23.85,22.89 23.54,22.58 19.2,22.58 19.05,22.73 19.05,26.97 19.27,27.2 23.87,27.2 24.53,26.54
GND on GND02: outline of 98 points within 7.57,2.54 121.23,69.49
GND on ART03: 93.37,55.88 97.96,55.88 98.29,55.55 98.29,51.49 97.23,50.42 94.84,50.42 93.04,52.22 93.04,55.55
GND on ART03: 93.21,39.67 95.91,39.67 96.39,39.19 96.39,35.51 95.37,34.49 93.32,34.49 92.78,35.03 92.78,39.24
GND on ART03: 93.32,16 97.28,16 98.95,17.68 98.95,21.84 100.22,23.11 100.22,24.03 98.07,26.19 94.89,26.19 94.53,25.83 94.53,21.49 92.96,19.91 92.96,16.36
GND on ART03: 12.26,69.42 29.26,69.42 30.2,68.48 30.2,62.51 26.59,58.9 22.58,58.9 22.09,58.42 13.36,58.42 12.26,59.51
GND on ART03: 117.75,66.6 115.39,64.24 107.39,64.24 106.68,63.53 106.68,59.89 107.46,59.11 116.66,59.11 118.16,57.61 118.16,54.48 114.88,51.21 106.37,51.21 105.28,52.3 105.28,53.57 103.35,55.5 100.3,55.5 98.55,57.25 92.99,57.25 92.66,57.58 92.66,59.92 89.73,62.84 89.73,66.42 88.57,67.59 88.57,69.29 88.74,69.47 117.75,69.47
GND on ART03: 94.74,49 100.48,49 101.39,49.91 101.39,51.69 103.02,51.69 103.5,51.21 103.5,22.96 103.12,22.58 98.34,27.36 98.34,37.74 99.79,39.19 99.79,41.33 94.38,46.74 94.38,48.64
GND on ART03: 73.96,69.19 81.91,69.19 83.03,68.07 84.91,68.07 85.42,67.56 85.42,63.4 74.29,63.4 73.33,64.36 73.33,68.55
GND on ART03: 23.82,43.92 25.04,43.92 25.04,43.33 24.86,43.15 23.8,43.15 23.57,42.93 23.57,42.55 23.64,42.47 24.79,42.47 25.09,42.77 25.42,42.77 25.42,43.92 25.62,43.92 25.78,43.76 25.78,41.15 25.47,40.84 23.87,40.84 23.8,40.92 23.8,41.45 22.93,42.32 22.93,43.03
GND on ART04: 63.47,60.22 72.92,60.22 75.05,62.36 75.05,69.16 75.33,69.44 117.62,69.44 117.75,69.32 117.75,66.6 115.52,64.36 111.07,64.36 110.92,64.21 107.59,64.21 106.96,63.58 106.96,53.64 106.24,52.93 94.71,52.93 91.94,50.16 84.4,50.16 84.15,50.42 84.15,51.74 84.12,51.77 57.93,51.77 56.92,52.78 56.92,53.67
GND on ART04: 67.61,13.28 68.17,12.73 68.17,12.62 67.69,12.14 61.97,12.14 61.85,12.27 61.85,12.78 61.49,13.13 57.43,13.13 57.15,12.85 57.15,12.34 57.06,12.26 56.8,12.26 56.46,12.6 56.46,13.28
GND on ART04: 16.48,27.69 23.59,27.69 24.28,27 24.28,22.1 17.34,22.1 15.97,23.47 15.97,27.18
GND on ART04: 38.6,44.78 44.14,44.78 44.42,44.5 44.42,40.13 43.66,39.37 38.43,39.37 38.38,39.42 38.38,44.55
GND on ART04: 94.71,19.15 95.96,19.15 96.62,18.49 96.62,15.09 96.54,15.01 96.54,14.05 97.48,13.11 102.03,13.11 102.18,12.95 102.18,12.27 98.14,8.23 98.12,8.23 97.18,7.29 91.46,7.29 88.92,9.83 88.92,11.99 89.48,12.55 89.48,16.28 90.32,17.12 94.33,17.12 94.61,17.4 94.61,19.05
GND on ART04: 103.6,7.9 108.81,7.9 109.9,6.81 116.25,6.81 117.6,5.46 117.6,2.44 117.57,2.41 102.56,2.41 102.13,2.84 102.13,6.43
GND on ART04: 31.92,37.54 34.67,37.54 36.01,36.2 36.01,34.8 35.76,34.54 35.76,26.21 35.56,26.01 34.84,26.01 31.64,29.21 31.64,37.26
GND on POW05: 106.4,7.54 103.12,10.82 103.12,30.79 98.78,35.13 98.78,48.59 100.71,50.52 100.71,57.31 99.52,58.5 81.03,58.5 74.85,64.67 42.95,64.67 42.95,68.12 42.49,68.58 39.7,68.58 39.09,69.19 29.43,69.19 28.83,68.58 14.02,68.58 12.8,67.36 12.21,67.36 12.21,69.49 117.85,69.49 117.85,66.63 115.38,64.16 107.84,64.16 106.98,63.3 106.98,60.19 107.86,59.31 117.52,59.31 118.56,58.26 118.56,53.73 115.71,50.88 108.68,50.88 107.03,49.23 107.03,45.87 110.68,42.21 113.49,42.21 115.37,44.09 119.35,44.09 121.23,42.21 121.23,29.67 120.69,29.13 118.47,29.13 115.01,32.59 111.6,32.59 109.7,30.69 109.7,23.39 110.71,22.38 113.31,22.38 115.44,24.51 119.7,24.51 120.95,23.26 120.95,9.78 120.74,9.58 118.06,9.58 116.18,11.46 109.97,11.46 109.14,10.62 109.14,7.87 109.46,7.54
GND on POW05: 59,8.13 59.88,7.25 59.88,3.24 59.2,2.57 30.45,2.57 29.74,3.28 29.74,7.95 29.92,8.13
GND_EARTH on TOP (solid shape): outline of 212 points within 5.64,63.64 11.35,69.35
GND_EARTH on TOP (solid shape): outline of 212 points within 5.64,0.64 11.35,6.36
GND_EARTH on TOP (solid shape): outline of 212 points within 118.64,63.64 124.35,69.35
GND_EARTH on TOP (solid shape): outline of 212 points within 118.64,0.64 124.35,6.36
GND_EARTH on BOTTOM (solid shape): outline of 212 points within 5.64,63.64 11.35,69.35
GND_EARTH on BOTTOM (solid shape): outline of 212 points within 5.64,0.64 11.35,6.36
GND_EARTH on BOTTOM (solid shape): outline of 212 points within 118.64,63.64 124.35,69.35
GND_EARTH on BOTTOM (solid shape): outline of 212 points within 118.64,0.64 124.35,6.36
GND_EARTH on TOP: 117.57,62.89 117.57,60.17 117.47,60.07 108.17,60.07 107.72,60.53 105.05,60.53 104.82,60.76 104.82,62.48 105.71,63.37 117.09,63.37
GND_EARTH on TOP: 71.7,4.65 73.94,4.65 74.14,4.45 74.14,2.44 73.91,2.21 71.9,2.21 71.57,2.54 71.57,4.52
GND_EARTH on TOP: outline of 119 points within 5.51,0.51 124.49,69.49
GND_EARTH on BOTTOM: outline of 103 points within 5.51,0.51 124.49,69.49
GND_EARTH on BOTTOM: 71.85,4.62 73.94,4.62 74.19,4.37 74.19,2.13 74.16,2.11 71.88,2.11 71.65,2.34 71.65,4.42
GND_EARTH on BOTTOM: 117.57,62.56 117.57,60.17 117.47,60.07 108.2,60.07 107.74,60.53 105.05,60.53 104.82,60.76 104.82,63.25 104.97,63.4 116.73,63.4
GND_EARTH on GND02, ART04, POW05: outline of 102 points within 5.51,0.51 124.49,69.49
GND_EARTH on ART03: outline of 100 points within 5.51,0.51 124.49,69.49
VDD_1V8 on TOP: 40.81,32.82 41.58,32.82 41.7,32.94 41.7,33.38 41.58,33.5 40.79,33.5 40.79,35.64 41.19,36.04 43.84,36.04 43.94,35.94 43.94,32.31 43.38,31.75 40.61,31.75 40.59,31.78 40.59,32.59
VDD_1V8 on BOTTOM: 14.19,28.6 15.67,28.6 16.33,29.26 16.33,29.79 15.97,30.15 15.16,30.15 14.19,29.18
VDD_1V8 on BOTTOM: 44.01,32.79 42.16,32.79 42.15,32.8 40.67,32.8 40.48,32.99 40.48,33.71 40.36,33.83 32.66,33.83 31.24,35.26 31.24,35.28 30.27,36.25 29.21,36.25 28.62,35.66 26.92,35.66 26.69,35.89 26.69,37.41 27.07,37.8 28.75,37.8 29.28,38.33 29.89,38.33 30.1,38.53 35.18,38.53 35.19,38.52 36.03,38.52 38.07,36.47 43.71,36.47 44.01,36.17
VDD_1V8 on BOTTOM: 26.09,31.2 26.36,30.94 26.36,30.35 26.01,30 24.1,30 23.87,30.23 23.87,31.2
VDD_1V8 on ART03: 41.25,35.84 43.33,35.84 43.89,35.28 43.89,33.6 43.56,33.27 41.45,33.27 40.92,33.81 40.92,35.51
VDD_1V8 on ART03: 13.38,41.02 15.87,41.02 16.51,40.39 16.51,38.89 17.32,38.07 17.32,37.73 17.17,37.58 15.45,37.58 15.44,37.59 14.98,37.59 14.19,38.38 13.48,38.38 13.2,38.66 13.2,40.84
VDD_1V8 on ART04: 28.7,37.31 28.7,35.61 28.6,35.51 27.76,35.51 27.43,35.18 27.43,34.85 25.75,33.17 25.75,28.93 24.91,28.09 16.35,28.09 15.35,29.1 15.35,32.5 15.82,32.97 15.82,35.69 16.35,36.22 16.35,37.85 16.58,38.07 17.27,38.07 17.52,37.82 23.21,37.82 23.55,37.48 23.55,36.79 24.02,36.32 24.35,36.32 25.75,37.72 28.29,37.72
VDD_3V3 on TOP: 59.13,63.27 60.75,63.27 60.88,63.14 60.88,60.07 60.8,59.99 59.28,59.99 58.97,60.3 58.97,63.12
VDD_3V3 on TOP: 98.47,28.98 99.77,28.98 99.89,28.85 99.89,27.43 99.77,27.3 98.47,27.3 98.32,27.46 98.32,28.83
VDD_3V3 on TOP: 31.54,31.34 29.33,31.34 29.1,31.57 29.1,32.69 29.23,32.82 31.52,32.82 31.75,32.59 31.75,31.55
VDD_3V3 on TOP: 101.01,31.39 102.21,31.39 102.46,31.14 102.46,29.97 102.21,29.72 101.04,29.72 100.88,29.87 100.88,31.27
VDD_3V3 on TOP: 39.7,40.26 42.13,40.26 43.96,38.43 43.96,36.7 39.16,36.7 39.16,39.73
VDD_3V3 on TOP: 89.18,13.61 92.71,13.61 93.04,13.28 93.04,12.73 92.86,12.55 89.38,12.55 89.12,12.8 89.12,13.56
VDD_3V3 on TOP: 100.63,11.73 101.57,11.73 101.57,10.39 101.44,10.26 100.45,10.26 100.38,10.34 100.38,11.48
VDD_3V3 on TOP: 39.19,63.7 39.82,63.7 40.56,62.97 40.56,60.15 40.46,60.05 39.65,60.05 39.11,60.58 39.11,63.63
VDD_3V3 on TOP: 101.19,23.19 102.36,23.19 102.46,23.29 102.46,24.69 102.26,24.89 101.06,24.89 101.06,23.32
VDD_3V3 on TOP: 9.27,60.4 10.97,60.4 11.12,60.25 11.12,59.23 10.87,58.98 9.34,58.98 9.22,59.11 9.22,60.35
VDD_3V3 on BOTTOM: 38.12,40.16 44.19,40.16 44.57,39.78 44.57,37.31 43.99,36.73 38.53,36.73 37.66,37.59 37.66,39.7
VDD_3V3 on BOTTOM: 91.25,13.68 91.59,13.34 91.59,12.83 91.49,12.73 89.3,12.73 89.16,12.87 89.16,13.35 89.33,13.51 89.84,13.51 90,13.68
VDD_3V3 on BOTTOM: 69.82,63.14 71.65,63.14 71.65,61.59 71.57,61.52 69.69,61.52 69.69,63.02
VDD_3V3 on BOTTOM: 47.93,14.4 47.82,14.3 46.91,14.3 46.91,16.15 47.04,16.28 47.77,16.28 47.93,16.13
VDD_3V3 on BOTTOM: 37.44,18.36 37.61,18.19 37.61,16.84 37.38,16.61 32.99,16.61 32.28,17.32 31.54,17.32 31.54,18.41 33.88,18.41 34.51,17.78 35.53,17.78 36.11,18.36
VDD_3V3 on BOTTOM: 59.05,62.18 60.58,62.18 60.78,61.98 60.78,61.06 60.7,60.99 59,60.99 58.97,61.01 58.97,62.1
VDD_3V3 on BOTTOM: 39.04,63.75 39.87,63.75 40.51,63.12 40.51,61.32 40.48,61.29 39.75,61.29 39.44,61.59 39.04,61.59
